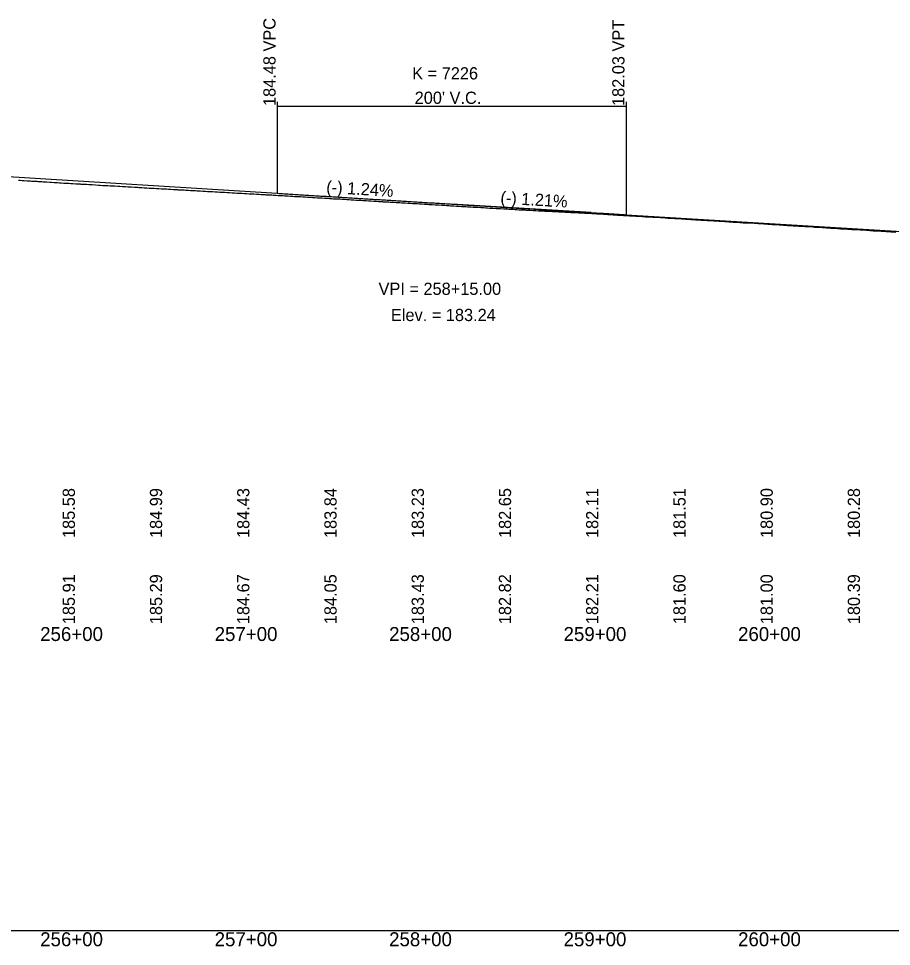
# Model space of a CAD drawing. Extents: x 1838386 to 1955906, y 719739 to 834437.
# Drawn here: x 1902930 to 1903430, y 825624 to 826156 of the extents above; entities that cross this region are included whole.
import ezdxf

# ---------------------------------------------------------------- set-up
doc = ezdxf.new("R2010")
doc.units = 0
for name, color, linetype in [('RD_DDB_GradeTX', 7, 'Continuous'), ('RD_DDB_Profile_EX', 7, 'Continuous'), ('RD_DDB_Profile_Lbl', 7, 'Continuous'), ('RD_DDB_Profile_PR', 7, 'Continuous'), ('RD_DDB_StaTX', 7, 'Continuous'), ('RD_DDB_StripGrade', 7, 'Continuous'), ('RD_DDB_VCLbl', 7, 'Continuous'), ('RD_GPK_Profile_Cell', 7, 'Continuous')]:
    doc.layers.add(name, color=color, linetype=linetype)

msp = doc.modelspace()

# ---------------------------------------------------------------- linework, layer by layer
at = {"layer": 'RD_DDB_GradeTX'}
for p in [(1903098.23, 826054.26), (1903257.93, 826044.47)]:
    msp.add_line(p, (1903178.08, 826049.31), dxfattribs=at)
at = {"layer": 'RD_DDB_Profile_EX'}
for points in [[(1902929.66, 826063.01), (1902930.79, 826062.95), (1902931.87, 826062.87), (1902932.92, 826062.82), (1902934.66, 826062.71), (1902936.44, 826062.6), (1902937.12, 826062.54), (1902937.45, 826062.53), (1902939, 826062.43), (1902940.26, 826062.38), (1902940.89, 826062.34), (1902942.17, 826062.26), (1902943.06, 826062.19), (1902943.93, 826062.15), (1902945.84, 826062.04), (1902947.79, 826061.92), (1902948.63, 826061.86), (1902950.2, 826061.75), (1902951.45, 826061.7), (1902952.04, 826061.66), (1902953.2, 826061.59), (1902954.24, 826061.51), (1902955.74, 826061.41), (1902957.04, 826061.36), (1902957.59, 826061.33), (1902958.67, 826061.26), (1902959.84, 826061.17), (1902960.96, 826061.12), (1902962.63, 826061.03), (1902964.36, 826060.92), (1902965.08, 826060.85), (1902965.43, 826060.84), (1902966.95, 826060.74), (1902968.23, 826060.7), (1902968.84, 826060.66), (1902970.08, 826060.59), (1902971.03, 826060.52), (1902972.02, 826060.48), (1902973.82, 826060.37), (1902975.59, 826060.27), (1902976.26, 826060.21), (1902976.61, 826060.19), (1902978.11, 826060.08), (1902979.42, 826060.04), (1902979.96, 826060.01), (1902981, 826059.94), (1902982.22, 826059.85), (1902983.42, 826059.8), (1902985, 826059.71), (1902986.6, 826059.62), (1902987.4, 826059.55), (1902987.8, 826059.53), (1902989.28, 826059.43), (1902990.6, 826059.38), (1902991.17, 826059.35), (1902992.35, 826059.28), (1902993.4, 826059.21), (1902994.43, 826059.16), (1902996.18, 826059.06), (1902997.95, 826058.95), (1902998.63, 826058.88), (1902998.98, 826058.87), (1903000.47, 826058.78), (1903001.78, 826058.73), (1903002.32, 826058.7), (1903003.35, 826058.64), (1903004.59, 826058.55), (1903005.85, 826058.5), (1903007.37, 826058.42), (1903008.86, 826058.32), (1903009.74, 826058.24), (1903010.17, 826058.23), (1903011.63, 826058.14), (1903012.98, 826058.09), (1903013.52, 826058.06), (1903014.62, 826058), (1903015.77, 826057.92), (1903016.93, 826057.86), (1903018.57, 826057.76), (1903020.23, 826057.66), (1903020.98, 826057.6), (1903021.36, 826057.59), (1903022.82, 826057.49)], [(1903022.82, 826057.49), (1903024.16, 826057.44), (1903024.66, 826057.41), (1903025.62, 826057.35), (1903026.97, 826057.25), (1903028.3, 826057.19), (1903029.76, 826057.12), (1903031.22, 826057.03), (1903032.11, 826056.95), (1903032.55, 826056.94), (1903034, 826056.84), (1903035.36, 826056.8), (1903035.9, 826056.77), (1903037.01, 826056.7), (1903038.16, 826056.62), (1903039.38, 826056.57), (1903040.95, 826056.48), (1903042.45, 826056.39), (1903043.3, 826056.32), (1903043.74, 826056.3), (1903045.15, 826056.21), (1903046.54, 826056.18), (1903047, 826056.15), (1903047.88, 826056.1), (1903049.34, 826056), (1903050.73, 826055.9), (1903052.14, 826055.86), (1903052.63, 826055.83), (1903053.62, 826055.77), (1903054.93, 826055.67), (1903056.2, 826055.62), (1903057.71, 826055.54), (1903059.3, 826055.45), (1903060.1, 826055.38), (1903060.51, 826055.37), (1903061.94, 826055.28), (1903063.32, 826055.23), (1903063.78, 826055.21), (1903064.65, 826055.15), (1903066.12, 826055.05), (1903067.61, 826054.99), (1903068.91, 826054.92), (1903070.21, 826054.84), (1903071.21, 826054.75), (1903071.7, 826054.73), (1903073.1, 826054.64), (1903074.51, 826054.59), (1903074.99, 826054.56), (1903076, 826054.5), (1903077.31, 826054.41), (1903078.66, 826054.34), (1903080.1, 826054.26), (1903081.5, 826054.17), (1903082.43, 826054.09), (1903082.9, 826054.07), (1903084.26, 826053.99), (1903085.7, 826053.94), (1903086.11, 826053.92), (1903086.9, 826053.86), (1903087.97, 826053.77), (1903088.5, 826053.75), (1903089.87, 826053.66), (1903091.3, 826053.61), (1903092.65, 826053.53), (1903094.07, 826053.43), (1903095.46, 826053.36), (1903096.86, 826053.28), (1903098.33, 826053.19), (1903099.21, 826053.11), (1903099.67, 826053.09), (1903101.05, 826053.01), (1903102.48, 826052.95), (1903102.89, 826052.92), (1903103.66, 826052.87), (1903105.29, 826052.75), (1903106.87, 826052.68), (1903108.07, 826052.62), (1903109.29, 826052.54), (1903110.34, 826052.44), (1903110.86, 826052.42), (1903112.23, 826052.33), (1903113.67, 826052.27), (1903114.12, 826052.25), (1903115.06, 826052.18), (1903116.47, 826052.08), (1903117.95, 826052), (1903119.25, 826051.92), (1903120.5, 826051.84), (1903121.53, 826051.75), (1903122.05, 826051.73), (1903123.38, 826051.65), (1903124.85, 826051.59), (1903125.22, 826051.57), (1903125.93, 826051.52), (1903127.09, 826051.41), (1903127.65, 826051.39), (1903128.98, 826051.31), (1903130.45, 826051.24), (1903130.85, 826051.22), (1903131.68, 826051.17), (1903133.24, 826051.05)], [(1903133.24, 826051.05), (1903134.72, 826050.97), (1903136.02, 826050.9), (1903137.36, 826050.81), (1903138.31, 826050.73), (1903138.82, 826050.71), (1903140.17, 826050.63), (1903141.64, 826050.58), (1903142.01, 826050.55), (1903142.71, 826050.51), (1903144.44, 826050.39), (1903146.17, 826050.3), (1903147.23, 826050.24), (1903148.3, 826050.17), (1903149.46, 826050.07), (1903150.02, 826050.05), (1903151.34, 826049.97), (1903152.83, 826049.91), (1903153.23, 826049.89), (1903154.07, 826049.83), (1903155.62, 826049.73), (1903157.24, 826049.65), (1903158.41, 826049.58), (1903159.55, 826049.51), (1903160.64, 826049.41), (1903161.21, 826049.39), (1903162.49, 826049.3), (1903164.02, 826049.23), (1903164.35, 826049.21), (1903164.96, 826049.17), (1903166.81, 826049.04), (1903168.58, 826048.95), (1903169.61, 826048.89), (1903170.68, 826048.82), (1903172.39, 826048.7), (1903174.03, 826048.63), (1903175.19, 826048.56), (1903176.39, 826048.48), (1903177.44, 826048.39), (1903177.98, 826048.37), (1903179.28, 826048.28), (1903180.79, 826048.2), (1903181.12, 826048.19), (1903181.76, 826048.15), (1903183.59, 826048.03), (1903185.46, 826047.94), (1903186.37, 826047.88), (1903187.28, 826047.83), (1903188.56, 826047.73), (1903189.18, 826047.71), (1903190.44, 826047.63), (1903191.98, 826047.56), (1903192.34, 826047.54), (1903193.06, 826047.49), (1903194.78, 826047.38), (1903196.5, 826047.29), (1903197.56, 826047.23), (1903198.62, 826047.16), (1903199.77, 826047.06), (1903200.37, 826047.04), (1903201.61, 826046.97), (1903203.46, 826046.89), (1903203.99, 826046.85), (1903205.98, 826046.72), (1903207.88, 826046.64), (1903208.76, 826046.59), (1903209.06, 826046.57), (1903209.69, 826046.53), (1903210.95, 826046.43), (1903211.56, 826046.41), (1903213.32, 826046.33), (1903214.35, 826046.28), (1903215.42, 826046.22), (1903216.56, 826046.12), (1903217.14, 826046.1), (1903218.39, 826046.03), (1903220.23, 826045.95), (1903220.79, 826045.92), (1903222.75, 826045.8), (1903224.73, 826045.71), (1903225.54, 826045.67), (1903226.35, 826045.63), (1903227.68, 826045.52), (1903228.33, 826045.51), (1903229.58, 826045.44), (1903231.14, 826045.39), (1903231.47, 826045.37), (1903232.14, 826045.33), (1903233.33, 826045.25), (1903233.94, 826045.23), (1903235.85, 826045.15), (1903237.01, 826045.1), (1903237.54, 826045.07), (1903239.52, 826044.96), (1903241.58, 826044.88), (1903242.32, 826044.84), (1903243.04, 826044.8), (1903244.43, 826044.7), (1903245.12, 826044.68), (1903246.33, 826044.61), (1903247.93, 826044.55)], [(1903247.93, 826044.55), (1903248.23, 826044.54), (1903248.84, 826044.51), (1903250.72, 826044.4), (1903252.68, 826044.3), (1903253.51, 826044.25), (1903254.3, 826044.21), (1903255.62, 826044.1), (1903256.31, 826044.08), (1903258.41, 826043.96), (1903259.1, 826043.92), (1903259.76, 826043.88), (1903261.2, 826043.76), (1903261.9, 826043.74), (1903263.1, 826043.67), (1903265, 826043.58), (1903265.6, 826043.55), (1903267.5, 826043.43), (1903268.69, 826043.35), (1903270.52, 826043.26), (1903270.95, 826043.23), (1903273.1, 826043.08), (1903275.22, 826042.97), (1903275.89, 826042.93), (1903276.58, 826042.89), (1903278.68, 826042.74), (1903279.87, 826042.67), (1903281.46, 826042.62), (1903282.32, 826042.57), (1903283.6, 826042.45), (1903284.27, 826042.43), (1903285.43, 826042.35), (1903287.26, 826042.27), (1903287.6, 826042.25), (1903289.14, 826042.11), (1903289.89, 826042.09), (1903292.04, 826042), (1903292.67, 826041.96), (1903293.35, 826041.92), (1903295.46, 826041.75), (1903297.54, 826041.66), (1903298.25, 826041.61), (1903298.98, 826041.57), (1903300.35, 826041.44), (1903301.06, 826041.42), (1903302.18, 826041.34), (1903304.02, 826041.26), (1903304.34, 826041.24), (1903305.89, 826041.09), (1903306.65, 826041.07), (1903307.79, 826040.99), (1903309.68, 826040.91), (1903310.14, 826040.88), (1903312.25, 826040.72), (1903314.39, 826040.61), (1903315.03, 826040.57), (1903315.65, 826040.53), (1903317.84, 826040.38), (1903320.15, 826040.27), (1903320.63, 826040.24), (1903321.09, 826040.21), (1903322.68, 826040.06), (1903323.44, 826040.04), (1903324.57, 826039.97), (1903326.45, 826039.89), (1903326.91, 826039.85), (1903328.32, 826039.71), (1903329.03, 826039.7), (1903331.3, 826039.58), (1903332, 826039.54), (1903332.32, 826039.51), (1903334.62, 826039.35), (1903336.98, 826039.23), (1903337.42, 826039.2), (1903337.85, 826039.17), (1903339.45, 826039.02), (1903340.21, 826039), (1903341.34, 826038.93), (1903343.22, 826038.85), (1903343.65, 826038.82), (1903345.07, 826038.68), (1903345.8, 826038.66), (1903346.91, 826038.59), (1903349, 826038.5), (1903351.41, 826038.32), (1903353.79, 826038.21), (1903354.2, 826038.19), (1903354.62, 826038.16), (1903356.99, 826037.98), (1903359.22, 826037.87), (1903359.78, 826037.84), (1903360.37, 826037.8), (1903361.83, 826037.66), (1903362.58, 826037.63), (1903363.68, 826037.56), (1903365.71, 826037.48), (1903368.19, 826037.29), (1903370.6, 826037.16), (1903370.98, 826037.14), (1903371.38, 826037.12), (1903373.77, 826036.93)], [(1903373.77, 826036.93), (1903376.03, 826036.83), (1903376.55, 826036.8), (1903377.08, 826036.76), (1903378.58, 826036.62), (1903379.38, 826036.6), (1903380.42, 826036.53), (1903382.4, 826036.44), (1903384.97, 826036.25), (1903386.01, 826036.18), (1903388.18, 826036.09), (1903390.56, 826035.91), (1903392.97, 826035.79), (1903393.35, 826035.77), (1903393.73, 826035.74), (1903395.33, 826035.59), (1903396.16, 826035.56), (1903397.17, 826035.5), (1903399.12, 826035.41), (1903400.9, 826035.24), (1903401.75, 826035.21), (1903402.78, 826035.15), (1903404.95, 826035.05), (1903407.35, 826034.87), (1903410.42, 826034.71), (1903412.08, 826034.55), (1903412.93, 826034.52), (1903415.88, 826034.36), (1903417.66, 826034.19), (1903418.53, 826034.16), (1903419.56, 826034.09), (1903421.71, 826033.99), (1903424.12, 826033.81), (1903425.15, 826033.74), (1903427.09, 826033.66), (1903429.73, 826033.47), (1903432.66, 826033.32)]]:
    msp.add_lwpolyline(points, dxfattribs=at)
at = {"layer": 'RD_DDB_Profile_PR'}
for p, q in [((1902916.84, 826065.51), (1903078.08, 826055.51)), ((1903278.08, 826043.25), (1903453.08, 826032.64))]:
    msp.add_line(p, q, dxfattribs=at)
msp.add_spline([(1903078.08, 826055.51), (1903082.08, 826055.27), (1903086.08, 826055.02), (1903090.08, 826054.77), (1903094.08, 826054.52), (1903098.08, 826054.28), (1903102.08, 826054.03), (1903106.08, 826053.78), (1903110.08, 826053.53), (1903114.08, 826053.29), (1903118.08, 826053.04), (1903122.08, 826052.79), (1903126.08, 826052.55), (1903130.08, 826052.3), (1903134.08, 826052.05), (1903138.08, 826051.81), (1903142.08, 826051.56), (1903146.08, 826051.31), (1903150.08, 826051.07), (1903154.08, 826050.82), (1903158.08, 826050.58), (1903162.08, 826050.33), (1903166.08, 826050.08), (1903170.08, 826049.84), (1903174.08, 826049.59), (1903178.08, 826049.35), (1903182.08, 826049.1), (1903186.08, 826048.86), (1903190.08, 826048.61), (1903194.08, 826048.37), (1903198.08, 826048.12), (1903202.08, 826047.88), (1903206.08, 826047.63), (1903210.08, 826047.39), (1903214.08, 826047.15), (1903218.08, 826046.9), (1903222.08, 826046.66), (1903226.08, 826046.41), (1903230.08, 826046.17), (1903234.08, 826045.93), (1903238.08, 826045.68), (1903242.08, 826045.44), (1903246.08, 826045.19), (1903250.08, 826044.95), (1903254.08, 826044.71), (1903258.08, 826044.46), (1903262.08, 826044.22), (1903266.08, 826043.98), (1903270.08, 826043.74), (1903274.08, 826043.49), (1903278.08, 826043.25)], degree=3, dxfattribs=at)
at = {"layer": 'RD_DDB_VCLbl'}
for p, q in [((1903078.08, 826108.01), (1903078.08, 826055.51)), ((1903078.08, 826105.51), (1903278.08, 826105.51)), ((1903278.08, 826108.01), (1903278.08, 826043.25))]:
    msp.add_line(p, q, dxfattribs=at)
at = {"layer": 'RD_GPK_Profile_Cell'}
msp.add_line((1878363.08, 825633.11), (1904963.08, 825633.11), dxfattribs=at)

# ---------------------------------------------------------------- texts
at = {"layer": 'RD_DDB_GradeTX'}
for s, rotation, p in [('(-) 1.24%', 356.4519, (1903106.02, 826055.78)), ('(-) 1.21%', 356.5309, (1903205.83, 826049.63))]:
    msp.add_text(s, height=7, rotation=rotation, dxfattribs=at).set_placement(p)
at = {"layer": 'RD_DDB_Profile_Lbl'}
for s, p in [('VPI = 258+15.00', (1903136.12, 825997.31)), ('Elev. = 183.24', (1903143.22, 825982.31))]:
    msp.add_text(s, height=7, dxfattribs=at).set_placement(p)
at = {"layer": 'RD_DDB_StaTX'}
for s, p in [('256+00', (1902942.18, 825799)), ('257+00', (1903042.18, 825799)), ('258+00', (1903142.18, 825799)), ('259+00', (1903242.18, 825799)), ('260+00', (1903342.18, 825799)), ('256+00', (1902942.18, 825624.11)), ('257+00', (1903042.18, 825624.11)), ('258+00', (1903142.18, 825624.11)), ('259+00', (1903242.18, 825624.11)), ('260+00', (1903342.18, 825624.11))]:
    msp.add_text(s, height=8, dxfattribs=at).set_placement(p)
at = {"layer": 'RD_DDB_StripGrade'}
for s, p in [('184.48 VPC', (1903077.08, 826105.51)), ('182.03 VPT', (1903277.08, 826105.51)), ('183.84', (1903112.08, 825858)), ('185.58', (1902962.08, 825858)), ('184.99', (1903012.08, 825858)), ('184.43', (1903062.08, 825858)), ('183.23', (1903162.08, 825858)), ('182.65', (1903212.08, 825858)), ('182.11', (1903262.08, 825858)), ('181.51', (1903312.08, 825858)), ('180.90', (1903362.08, 825858)), ('180.28', (1903412.08, 825858)), ('185.91', (1902962.08, 825808.62)), ('185.29', (1903012.08, 825808.62)), ('184.67', (1903062.08, 825808.62)), ('184.05', (1903112.08, 825808.62)), ('183.43', (1903162.08, 825808.62)), ('182.82', (1903212.08, 825808.62)), ('182.21', (1903262.08, 825808.62)), ('181.60', (1903312.08, 825808.62)), ('181.00', (1903362.08, 825808.62)), ('180.39', (1903412.08, 825808.62))]:
    msp.add_text(s, height=7, rotation=90, dxfattribs=at).set_placement(p)
at = {"layer": 'RD_DDB_VCLbl'}
for s, p in [('K = 7226', (1903155.42, 826120.76)), ("200' V.C.", (1903156.83, 826106.76))]:
    msp.add_text(s, height=7, dxfattribs=at).set_placement(p)

doc.saveas('drawing.dxf')
